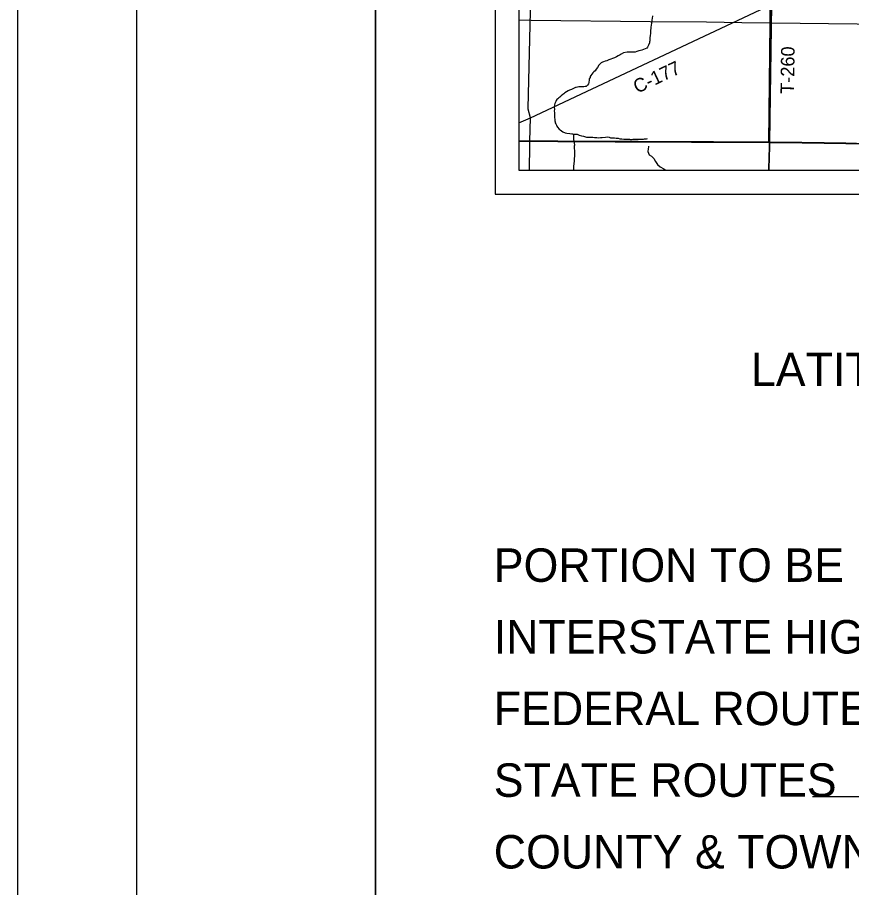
# Model space of a CAD drawing. Extents: x 0 to 34, y 0 to 22.
# Drawn here: x 0 to 3.493, y 11.097 to 14.74 of the extents above; entities that cross this region are included whole.
import ezdxf

# ---------------------------------------------------------------- set-up
doc = ezdxf.new("R2010")
doc.units = 0
for name, color, linetype in [('GM_X_County_Road', 7, 'Continuous'), ('GM_X_County_Road_Text', 7, 'Continuous'), ('GM_X_Minor_River', 7, 'Continuous'), ('GM_X_Rail_Line', 7, 'Continuous'), ('GM_X_Section', 7, 'Continuous'), ('GM_X_State_Route', 7, 'Continuous'), ('GM_X_Township_Road', 7, 'Continuous'), ('GM_X_Township_Road_Text', 7, 'Continuous'), ('SH_Border', 7, 'Continuous'), ('SH_Cut_Line', 7, 'Continuous'), ('SH_Data', 7, 'Continuous'), ('SH_Text', 7, 'Continuous')]:
    doc.layers.add(name, color=color, linetype=linetype)

msp = doc.modelspace()

# ---------------------------------------------------------------- linework, layer by layer
at = {"layer": 'GM_X_County_Road'}
for p, q in [((2.1481, 14.3195), (3.1578, 14.7935)), ((2.1, 14.2214), (2.1455, 14.2212))]:
    msp.add_line(p, q, dxfattribs=at)
for points in [[(2.1435, 14.1), (2.1436, 14.106), (2.1455, 14.1986), (2.1455, 14.2147), (2.1455, 14.2212)], [(2.1455, 14.2212), (2.1892, 14.221), (2.2632, 14.2205), (2.3546, 14.22), (2.4522, 14.2196), (2.5032, 14.2194), (2.5653, 14.219), (2.5989, 14.219), (2.6579, 14.2187), (2.7338, 14.2184), (2.8227, 14.218), (2.8743, 14.2178), (2.9153, 14.2176), (3.0595, 14.217), (3.0956, 14.2169), (3.1493, 14.2166)], [(3.1493, 14.2166), (3.1515, 14.2166), (3.2852, 14.2149), (3.3044, 14.2146), (3.3778, 14.2136), (3.4331, 14.2126), (3.4692, 14.2121), (3.5139, 14.2114), (3.586, 14.2106), (3.6556, 14.21)]]:
    msp.add_lwpolyline(points, dxfattribs=at)
at = {"layer": 'GM_X_Minor_River'}
for points in [[(2.659, 14.7467), (2.6575, 14.7346), (2.6568, 14.7296), (2.6557, 14.7243), (2.6553, 14.7205), (2.6546, 14.7159), (2.6539, 14.7072), (2.6524, 14.6981), (2.6521, 14.6928), (2.6513, 14.6855), (2.6506, 14.6791), (2.6503, 14.6734), (2.6488, 14.662), (2.6481, 14.6555), (2.6477, 14.6506), (2.6474, 14.6468), (2.6474, 14.6418), (2.647, 14.6369), (2.6463, 14.6327), (2.6425, 14.624), (2.638, 14.6152), (2.6358, 14.6114), (2.6146, 14.6022), (2.6089, 14.6006), (2.6013, 14.5994), (2.5937, 14.5971), (2.5869, 14.5944), (2.5782, 14.5936), (2.5664, 14.5943), (2.5523, 14.5935), (2.5383, 14.5915), (2.5277, 14.5862), (2.5236, 14.5827), (2.516, 14.5785), (2.508, 14.5743), (2.5001, 14.5705), (2.4917, 14.5678), (2.4842, 14.5651), (2.4762, 14.5624), (2.4679, 14.5585), (2.4603, 14.5558), (2.4539, 14.5535), (2.4497, 14.552), (2.4448, 14.5501), (2.4395, 14.5459), (2.435, 14.5398), (2.4285, 14.5306), (2.4236, 14.5226), (2.4184, 14.5161), (2.4135, 14.5116), (2.4097, 14.507), (2.4055, 14.5016), (2.4014, 14.4959), (2.3984, 14.4917), (2.3976, 14.4879), (2.3942, 14.4822), (2.3935, 14.478), (2.3924, 14.4666), (2.3917, 14.4609), (2.3875, 14.4556), (2.3815, 14.451), (2.3769, 14.4506), (2.3716, 14.4494), (2.3644, 14.449), (2.3565, 14.4486), (2.35, 14.4486), (2.3447, 14.4478), (2.3398, 14.4462), (2.336, 14.4455), (2.3314, 14.4439), (2.3201, 14.4385), (2.3117, 14.4355), (2.3057, 14.4328), (2.2992, 14.4286), (2.2924, 14.424), (2.2883, 14.4198), (2.2834, 14.4163), (2.2769, 14.411), (2.2713, 14.406), (2.2667, 14.4033), (2.263, 14.3988), (2.2584, 14.3957), (2.2562, 14.3919), (2.2539, 14.3873), (2.2505, 14.3793), (2.2487, 14.374), (2.2483, 14.3679), (2.248, 14.3622), (2.2484, 14.355), (2.248, 14.3474), (2.2481, 14.3413), (2.2485, 14.3356), (2.2489, 14.325), (2.2493, 14.3201), (2.2501, 14.3129), (2.2505, 14.3068), (2.2513, 14.3018)], [(2.2513, 14.3018), (2.2521, 14.298), (2.2547, 14.2943), (2.2574, 14.2878), (2.259, 14.284), (2.2617, 14.2799), (2.2678, 14.2723), (2.272, 14.2689), (2.2781, 14.2647), (2.2841, 14.2602), (2.2937, 14.2565), (2.3001, 14.255), (2.3127, 14.2535), (2.3218, 14.2524), (2.3259, 14.2517), (2.3316, 14.2509), (2.3362, 14.2506), (2.3438, 14.2502), (2.3518, 14.2472), (2.3624, 14.2439), (2.37, 14.242), (2.378, 14.2398), (2.383, 14.2383), (2.3875, 14.2379), (2.4035, 14.238), (2.4091, 14.2376), (2.416, 14.2365), (2.4259, 14.2362), (2.4346, 14.2355), (2.4418, 14.2363), (2.449, 14.2371), (2.4627, 14.2383), (2.4695, 14.2391), (2.4775, 14.2376), (2.4828, 14.2361), (2.49, 14.2354), (2.4995, 14.235), (2.5071, 14.2347), (2.5154, 14.234), (2.5227, 14.2317), (2.5303, 14.2306), (2.5394, 14.2299), (2.5477, 14.2296), (2.5568, 14.2296), (2.5622, 14.2293), (2.5671, 14.2289), (2.5717, 14.2289), (2.577, 14.2293), (2.5868, 14.2294), (2.5956, 14.2298), (2.5997, 14.2302), (2.6051, 14.2298), (2.6096, 14.2299), (2.6157, 14.2303), (2.6214, 14.2303), (2.6252, 14.2307), (2.6305, 14.2315), (2.6346, 14.2319), (2.6388, 14.233)], [(2.3333, 14.2043), (2.3307, 14.2223), (2.33, 14.2254), (2.33, 14.228), (2.3297, 14.2315), (2.3293, 14.2345), (2.3296, 14.2511)], [(2.3318, 14.2043), (2.3317, 14.2003), (2.3315, 14.1928), (2.3318, 14.1807), (2.3322, 14.1712), (2.3321, 14.1583), (2.3317, 14.1484), (2.3306, 14.1385), (2.3294, 14.1271), (2.3286, 14.1165), (2.3286, 14.1)], [(2.6421, 14.2011), (2.6419, 14.1981), (2.6406, 14.1888), (2.6398, 14.1781), (2.6451, 14.1641), (2.6549, 14.1591), (2.664, 14.1496), (2.6716, 14.1363), (2.6799, 14.1241), (2.6916, 14.1143), (2.7064, 14.1055), (2.7154, 14.1)]]:
    msp.add_lwpolyline(points, dxfattribs=at)
at = {"layer": 'GM_X_Rail_Line'}
msp.add_lwpolyline([(2.1, 14.729), (2.1509, 14.7286), (2.6493, 14.723), (2.8845, 14.7204), (3.0329, 14.7186), (3.1572, 14.7171), (3.5158, 14.7132), (3.8511, 14.7095), (3.8755, 14.7092)], dxfattribs=at)
at = {"layer": 'GM_X_Section'}
msp.add_lwpolyline([(3.1571, 15.217), (4.1541, 15.2001), (4.1481, 14.2013), (3.1458, 14.2165)], close=True, dxfattribs=at)
at = {"layer": 'GM_X_State_Route'}
msp.add_line((2.1388, 14.359), (2.1579, 15.2243), dxfattribs=at)
for points in [[(2.138, 14.3149), (2.1481, 14.3195), (2.1387, 14.355), (2.1388, 14.359)], [(2.1, 14.2978), (2.1289, 14.3107), (2.138, 14.3149)]]:
    msp.add_lwpolyline(points, dxfattribs=at)
at = {"layer": 'GM_X_Township_Road'}
msp.add_line((2.1455, 14.2212), (2.1481, 14.3195), dxfattribs=at)
for points in [[(2.1, 20.2296), (2.1, 14.2219), (2.1453, 14.2217), (2.189, 14.2216), (2.263, 14.2211), (2.3544, 14.2206), (2.452, 14.2201), (2.5029, 14.22), (2.5651, 14.2195), (2.5987, 14.2195), (2.6577, 14.2192), (2.7336, 14.2189), (2.8225, 14.2185), (2.8741, 14.2183), (2.9151, 14.2182), (3.0593, 14.2176), (3.0954, 14.2174), (3.1491, 14.2171), (3.1576, 14.794)], [(3.1493, 14.2166), (3.1578, 14.7935), (3.163, 15.2153)], [(3.1576, 14.794), (3.1491, 14.2171), (3.1513, 14.2171), (3.2849, 14.2154), (3.3042, 14.2152), (3.3776, 14.2141), (3.4329, 14.2132), (3.4689, 14.2127), (3.5137, 14.212)], [(3.5137, 14.212), (3.4689, 14.2127), (3.4329, 14.2132), (3.3776, 14.2141), (3.3042, 14.2152), (3.2849, 14.2154), (3.1513, 14.2171), (3.1491, 14.2171), (3.149, 14.2126), (3.1486, 14.1927), (3.1481, 14.1592), (3.1468, 14.1), (8.9, 14.1)], [(3.1471, 14.1), (3.1483, 14.1586), (3.1488, 14.1922), (3.1492, 14.2121), (3.1493, 14.2166)]]:
    msp.add_lwpolyline(points, dxfattribs=at)
msp.add_lwpolyline([(2.1, 14.2219), (2.1, 14.1), (3.1468, 14.1), (3.1481, 14.1592), (3.1486, 14.1927), (3.149, 14.2126), (3.1491, 14.2171), (3.0954, 14.2174), (3.0593, 14.2176), (2.9151, 14.2182), (2.8741, 14.2183), (2.8225, 14.2185), (2.7336, 14.2189), (2.6577, 14.2192), (2.5987, 14.2195), (2.5651, 14.2195), (2.5029, 14.22), (2.452, 14.2201), (2.3544, 14.2206), (2.263, 14.2211), (2.189, 14.2216), (2.1453, 14.2217)], close=True, dxfattribs=at)
at = {"layer": 'SH_Border'}
for points in [[(0.5, 21.5), (1.5, 21.5), (1.5, 0.5), (0.5, 0.5)], [(1.5, 21.5), (33.5, 21.5), (33.5, 0.5), (1.5, 0.5)]]:
    msp.add_lwpolyline(points, close=True, dxfattribs=at)
at = {"layer": 'SH_Cut_Line'}
msp.add_lwpolyline([(0, 0), (34, 0), (34, 22), (0, 22)], close=True, dxfattribs=at)
for points in [[(2.1, 20.9), (2.1, 14.2219), (2.1453, 14.2217), (2.189, 14.2216), (2.263, 14.2211), (2.3544, 14.2206), (2.452, 14.2201), (2.5029, 14.22), (2.5651, 14.2195), (2.5987, 14.2195), (2.6577, 14.2192), (2.7336, 14.2189), (2.8225, 14.2185), (2.8741, 14.2183), (2.9151, 14.2182), (3.0593, 14.2176), (3.0954, 14.2174), (3.1491, 14.2171), (3.1513, 14.2171), (3.2849, 14.2154), (3.3042, 14.2152), (3.3776, 14.2141), (3.4329, 14.2132), (3.4689, 14.2127), (3.5137, 14.212)], [(3.5137, 14.212), (3.4689, 14.2127), (3.4329, 14.2132), (3.3776, 14.2141), (3.3042, 14.2152), (3.2849, 14.2154), (3.1513, 14.2171), (3.1491, 14.2171), (3.0954, 14.2174), (3.0593, 14.2176), (2.9151, 14.2182), (2.8741, 14.2183), (2.8225, 14.2185), (2.7336, 14.2189), (2.6577, 14.2192), (2.5987, 14.2195), (2.5651, 14.2195), (2.5029, 14.22), (2.452, 14.2201), (2.3544, 14.2206), (2.263, 14.2211), (2.189, 14.2216), (2.1453, 14.2217), (2.1, 14.2219), (2.1, 14.1), (8.9, 14.1)]]:
    msp.add_lwpolyline(points, dxfattribs=at)
at = {"layer": 'SH_Data'}
for p, q in [((2, 21), (2, 14)), ((2.1, 20.9), (2.1, 14.1)), ((2.1, 14.1), (8.9, 14.1)), ((2.1, 14.1), (2.1, 14.1)), ((2, 14), (9, 14)), ((7.7, 11.4767), (3.3288, 11.4767))]:
    msp.add_line(p, q, dxfattribs=at)

# ---------------------------------------------------------------- texts
at = {"layer": 'GM_X_County_Road_Text'}
msp.add_text('C-177', height=0.05682, rotation=25.3333, dxfattribs=at).set_placement((2.5952, 14.4199))
at = {"layer": 'GM_X_Township_Road_Text'}
msp.add_text('T-260', height=0.05682, rotation=89.1579, dxfattribs=at).set_placement((3.2515, 14.4193))
at = {"layer": 'SH_Text'}
for s, p in [('LATITUDE:  41°30\'05"     LONGITUDE:  -82°94\'10"', (3.071, 13.1959)), ('PORTION TO BE IMPROVED', (1.9944, 12.3767)), ('INTERSTATE HIGHWAY', (1.9944, 12.0767)), ('FEDERAL ROUTES', (1.9944, 11.7767)), ('STATE ROUTES', (1.9944, 11.4767)), ('COUNTY & TOWNSHIP ROADS', (1.9944, 11.1767))]:
    msp.add_text(s, height=0.14, dxfattribs=at).set_placement(p)

doc.saveas('drawing.dxf')
